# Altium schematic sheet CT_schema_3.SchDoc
size 293 x 134 mm
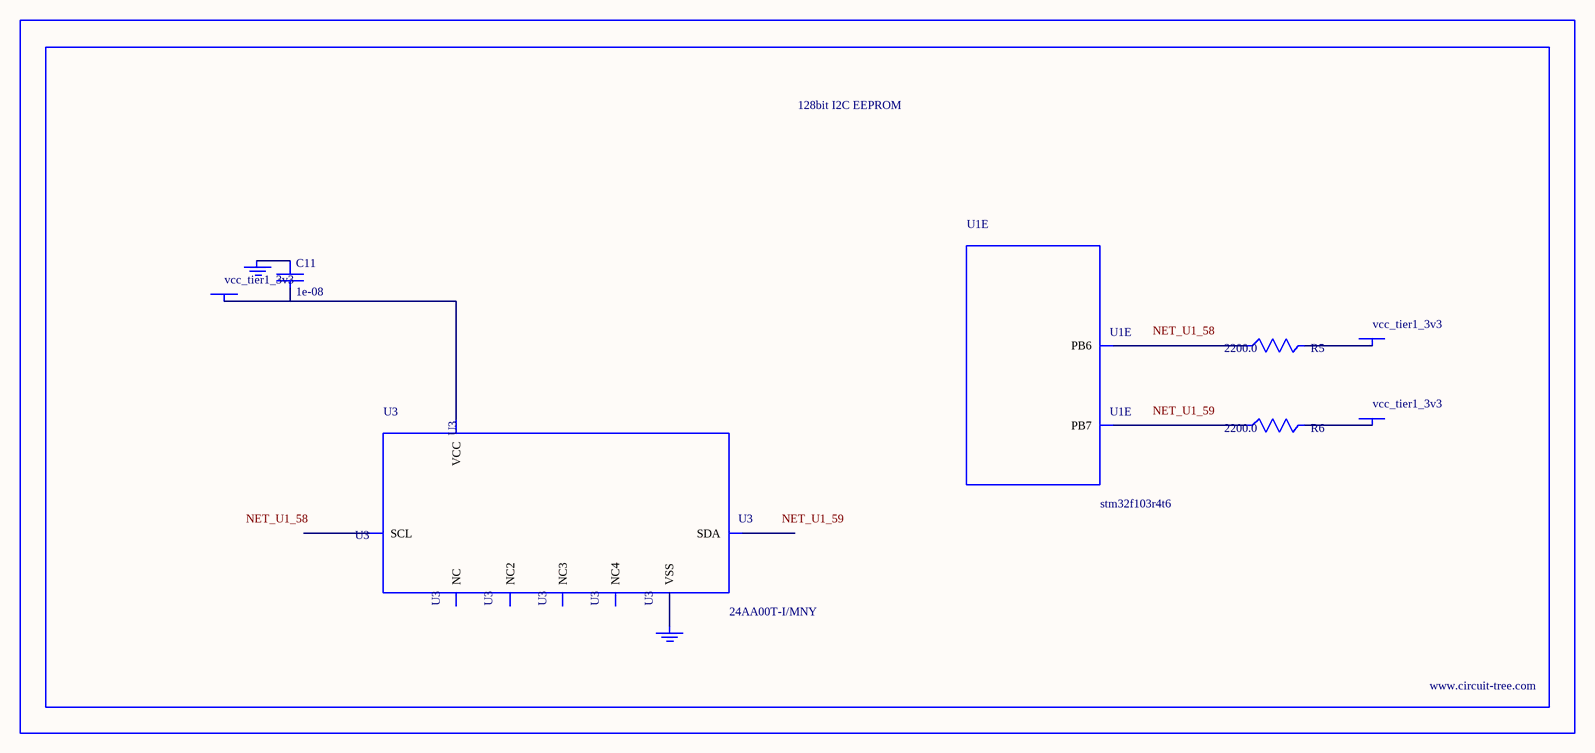
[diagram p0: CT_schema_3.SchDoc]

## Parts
BORDER2  (no value)
C11  1e-08  [C0402]
GND_INSTANCE_2_0  (no value)
GND_INSTANCE_2_1  (no value)
POWER_INSTANCE_2_0  vcc_tier1_3v3
POWER_INSTANCE_2_1  vcc_tier1_3v3
POWER_INSTANCE_2_2  vcc_tier1_3v3
R5  2200.0  [R0603]
R6  2200.0  [R0603]
U1  stm32f103r4t6  [LQFP64]  (part E of 6)
U3  24AA00T-I/MNY  [TDFN-8/6MM]

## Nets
NetC11_1: C11.1 GND_INSTANCE_2_0.0(GND)
NetC11_2: C11.2 POWER_INSTANCE_2_0.0(PWR) U3.8(VCC)
NetGND_INSTANCE_2_1_0: GND_INSTANCE_2_1.0(GND) U3.4(VSS)
NetPOWER_INSTANCE_2_1_0: POWER_INSTANCE_2_1.0(PWR) R5.2
NetPOWER_INSTANCE_2_2_0: POWER_INSTANCE_2_2.0(PWR) R6.2
NetR5_1: R5.1 U1.58(PB6)
NetR6_1: R6.1 U1.59(PB7)

Not connected (* = marked no-connect by the designer): U3 1(NC) 2(NC2) 3(NC3) 5(SDA) 6(SCL) 7(NC4)

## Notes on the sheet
- Labels drawn without touching a wire or pin: NET_U1_58, NET_U1_59

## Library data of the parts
BORDER2 = BORDER_PAGE2
C11 = C0402C103K3RAC
GND_INSTANCE_2_0 GND_INSTANCE_2_1 = GND
POWER_INSTANCE_2_0-POWER_INSTANCE_2_2 = PWR
R5 R6 = RC0603JR-072K2L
